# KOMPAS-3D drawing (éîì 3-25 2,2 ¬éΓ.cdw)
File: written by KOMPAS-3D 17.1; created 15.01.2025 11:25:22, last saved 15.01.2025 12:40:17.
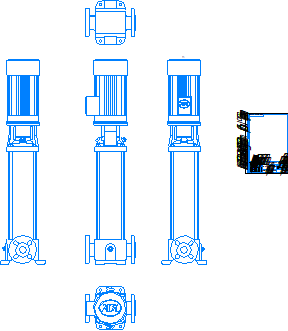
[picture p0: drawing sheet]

Sheet 1: A4, portrait

Title block, sheet 1: name: ВМН 3-25 2,2 кВт; designation: ВМН 3-25 2,2 кВт; material: Сталь 10  ГОСТ 1050-2013; mass: 0,03; sheets: 1; sheet format: A4; stored path: \\adlc.lan\data\АДЛ_ПКД\3D-модели\ADL production\Насосы ГРАНПАМП\Насосы ВМН\ВМН3\KOMPAS 3D\ВМН 3-25 2,2 кВт.cdw

Views: Проекционный вид 2, Проекционный вид 3, Проекционный вид 4, Проекционный вид 5
Referenced files in \\adlc.lan\data\АДЛ_ПКД\3D-модели\ADL production\Насосы ГРАНПАМП\Насосы ВМН\ВМН3\KOMPAS 3D\: ВМН 3-25 2,2 кВт.m3d
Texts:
  Andrey
  АДЛ
Dimensions and other numbers on the sheet: 1:1; 1; 0,03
